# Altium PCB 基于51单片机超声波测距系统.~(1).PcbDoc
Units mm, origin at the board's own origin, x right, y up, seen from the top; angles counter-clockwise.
Board outline 152.4 x 101.6 mm, 2 copper layers (Top Layer, Bottom Layer); 25 components, 33 nets, 135 pads, 0 vias.
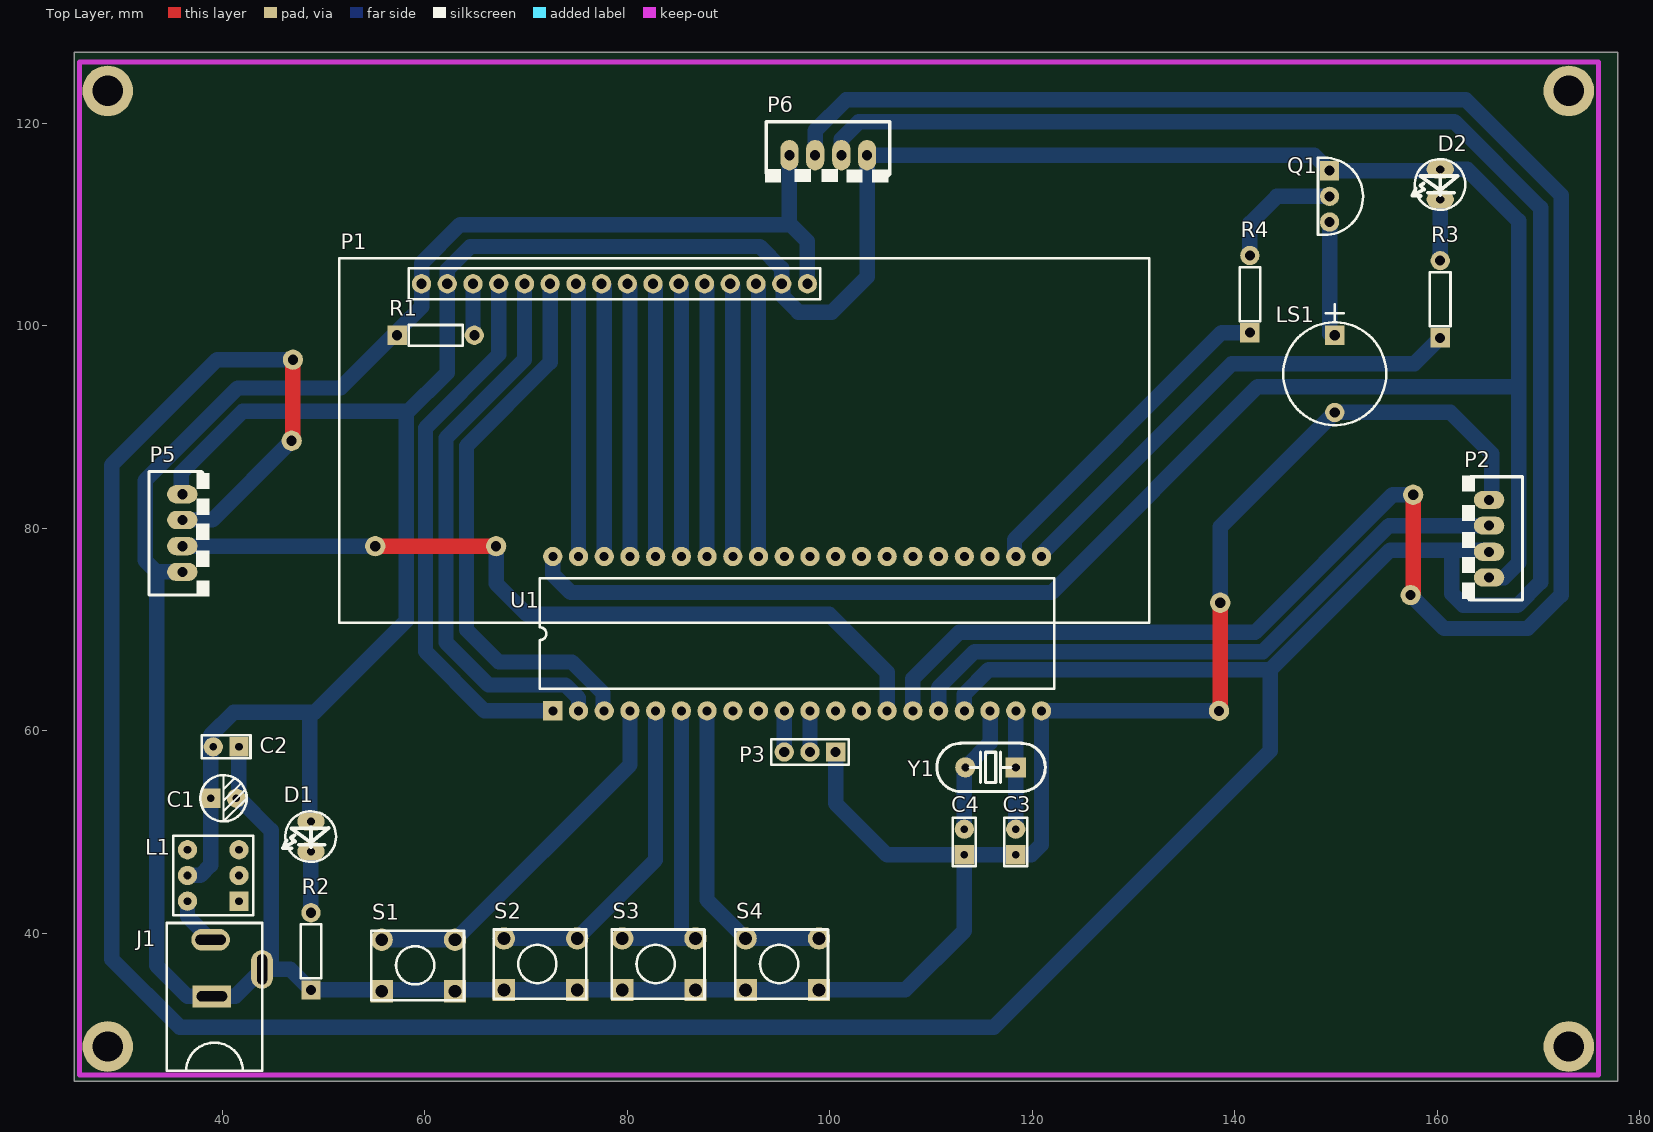
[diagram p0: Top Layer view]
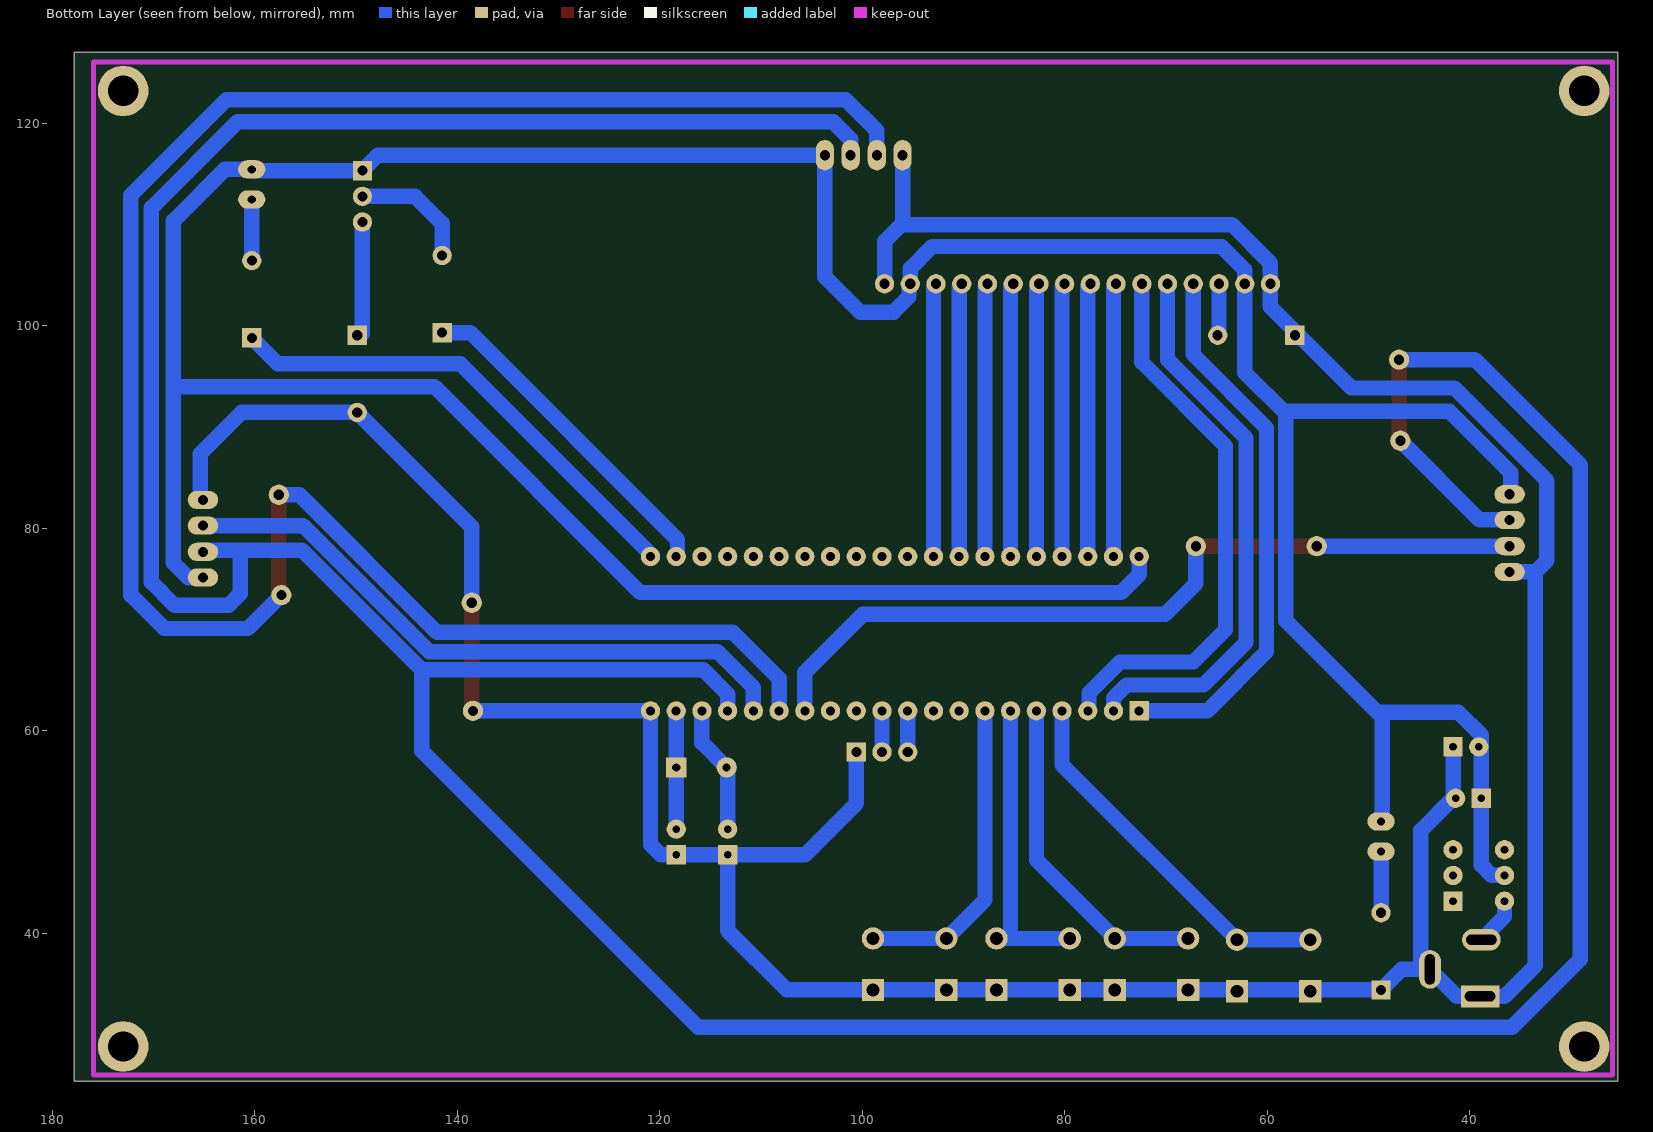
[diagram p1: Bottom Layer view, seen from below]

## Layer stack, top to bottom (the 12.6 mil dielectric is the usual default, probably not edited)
Top Layer: signal copper 0.0356
Dielectric: dielectric 0.32, FR-4, Dk 4.8
Bottom Layer: signal copper 0.0356

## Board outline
25.4,25.4 177.8,25.4 177.8,127 25.4,127

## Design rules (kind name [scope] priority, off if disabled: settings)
Clearance [All] p1: gap=0.254
FabricationTestPointUsage TestPointUsage [All] p1: valid=0 allowmultiple=FALSE
FabricationTestpoint Testpoint [All] p1: side=3 testpointundercomponent=TRUE minsize=1.016 maxsize=2.54 preferedsize=1.524 minholesize=0 maxholesize=1.016 preferedholesize=0.813 testpointgrid=0.025 allowsidetop=TRUE allowsidebottom=TRUE usegrid=TRUE gridtolerance=0
PolygonConnect [All] p1: connectstyle=Relief reliefconductorwidth=0.254 reliefentries=4 polygonreliefangle="90 Angle"
RoutingVias [All] p1: holewidth=0.711 width=1.27 viastyle="Through Hole" minholewidth=0.711 minwidth=1.27 maxholewidth=0.711 maxwidth=1.27
SilkscreenOverComponentPads [All] p1: minsilkscreentomaskgap=0.254
SolderMaskExpansion [All] p1: expansion=0.102
Width [All] p1: maxlimit=2.54 minlimit=0.254 preferedwidth=0.254
25 further rules are at their usual default settings.

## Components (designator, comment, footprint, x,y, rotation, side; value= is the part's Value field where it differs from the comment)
C1 "47uF" 电解电容 40.132,53.34 r0 top
C2 "104" 瓷片电容 39.116,58.42 r180 top
C3 "22pF" 瓷片电容 118.364,50.292 r90 top
C4 "22pF" 瓷片电容 113.284,50.292 r90 top
D1 "LED" 发光二极管 48.768,49.784 r0 top
D2 "LED" 发光二极管 160.274,114.173 r0 top
J1 "PWR2.5" 电源接头 36.322,31.496 r90 top
L1 "电源开关" 开关 39.37,45.72 r180 top
LS1 "Speaker" 蜂鸣器 149.86,99.06 r270 top
P1 "1602" LCD1602液晶 84.328,83.82 r0 top
P2 "Header 4" 4P座 165.1,82.804 r270 top
P3 "程序下载接口" 下载器 100.584,57.912 r180 top
P5 "Header 4" 4P座 36.068,75.692 r90 top
P6 "Header 4" 4P座 96.012,116.84 r0 top
Q1 "8550" 三极管 149.606,115.189 r0 top
R1 "3K" 电阻 60.96,99.06 r90 top
R2 "10K" 电阻 48.768,38.1 r180 top
R3 "1K" 电阻 160.274,102.489 r180 top
R4 "100" 电阻 141.478,102.997 r180 top
S1 "" 按键 59.055,36.957 r90 top
S2 "" 按键 71.12,37.084 r90 top
S3 "" 按键 82.804,37.084 r90 top
S4 "" 按键 94.996,37.084 r90 top
U1 "STC89C51" 51单片机 72.644,61.976 r90 top
Y1 "11.0592MHz" 晶振 118.364,56.388 r180 top

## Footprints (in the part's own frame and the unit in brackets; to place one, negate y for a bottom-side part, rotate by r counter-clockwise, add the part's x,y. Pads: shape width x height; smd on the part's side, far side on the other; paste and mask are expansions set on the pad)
4P座 [mil]
  oval 71x118 hole 39.37: 1(0,0) 2(100,0) 3(202,0) 4(302,0)
  silkscreen extent -96,-106 390,130
51单片机 [mil]
  rect 75x75 hole 35: 1(0,0)
  round 75 hole 35: 2(0,-100) 3(0,-200) 4(0,-300) 5(0,-400) 6(0,-500) 7(0,-600) 8(0,-700) 9(0,-800) 10(0,-900) 11(0,-1000) 12(0,-1100) 13(0,-1200) 14(0,-1300) 15(0,-1400) 16(0,-1500) 17(0,-1600) 18(0,-1700) 19(0,-1800) 20(0,-1900) 21(600,-1900) 22(600,-1800) 23(600,-1700) 24(600,-1600) 25(600,-1500) 26(600,-1400) 27(600,-1300) 28(600,-1200) 29(600,-1100) 30(600,-1000) 31(600,-900) 32(600,-800) 33(600,-700) 34(600,-600) 35(600,-500) 36(600,-400) 37(600,-300) 38(600,-200) 39(600,-100) 40(600,0)
  silkscreen extent 85,-1950 515,50
LCD1602液晶 [mm]
  round 1.905 hole 1: 1(-24.638,20.32) 2(-22.098,20.32) 3(-19.558,20.32) 4(-17.018,20.32) 5(-14.478,20.32) 6(-11.938,20.32) 7(-9.398,20.32) 8(-6.858,20.32) 9(-4.318,20.32) 10(-1.778,20.32) 11(0.762,20.32) 12(3.302,20.32) 13(5.842,20.32) 14(8.382,20.32) 15(10.922,20.32) 16(13.462,20.32)
  silkscreen extent -32.77,-13.16 47.23,22.84
三极管 [mil]
  rect 75x75 hole 39: 1(-10,5)
  round 75 hole 39: 2(-10,-95) 3(-10,-195)
  silkscreen extent -55,-245 120,55
下载器 [mil]
  rect 75x75 hole 39: 1(0,0)
  round 75 hole 39: 2(100,0) 3(200,0)
  silkscreen extent -50,-50 250,50
发光二极管 [mil]
  oval 106x71 hole 31.5: 1(0,50) 2(0,-67)
  silkscreen extent -108,-107 98,89
开关 [mil]
  rect 75x75 hole 30: 1(-90,100)
  round 75 hole 30: 2(110,100) 3(-90,0) 4(110,0) 5(-90,-100) 6(110,-100)
  silkscreen extent -145,-155 165,155
按键 [mm]
  rect 2.2x2.2 hole 1.27: 1(-2.667,3.302) 1(-2.667,-3.937)
  round 2.2 hole 1.27: 2(2.413,3.302) 2(2.413,-3.937)
  silkscreen extent -3.56,-4.83 3.3,4.32
晶振 [mm]
  rect 2x2 hole 0.8: 1(0,0)
  round 2 hole 0.8: 2(4.978,0)
  silkscreen extent -2.92,-2.41 7.8,2.39
瓷片电容 [mil]
  rect 75x75 hole 30: 1(-100,0)
  round 75 hole 30: 2(0,0)
  silkscreen extent -145,-45 45,45
电源接头 [mil]
  oval 85x150 hole 39.37 slot 118.11 at 90 deg: 1(310,-100)
  rect 85x150 hole 39.37 slot 118.11 at 90 deg: 2(90,-105)
  oval 150x85 hole 39.37 slot 118.11 at 0 deg: 2(195,-300)
  silkscreen extent -200,-300 375,70
电解电容 [mil]
  rect 75x75 hole 30: 1(-50,0)
  round 75 hole 30: 2(50,0)
  silkscreen extent -90,-90 90,90
电阻 [mil]
  rect 75x75 hole 39: 1(0,145)
  round 75 hole 39: 2(0,-155)
  silkscreen extent -40,-110 40,100
蜂鸣器 [mil]
  rect 75x75 hole 39: 1(0,0)
  round 75 hole 39: 2(300,0)
  silkscreen extent -120,-200 350,200

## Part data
C1: library part "Cap Pol1", "Polarized Capacitor (Radial)"
C2 C3 C4: library part Cap, "Capacitor"
D1 D2: library part LED0, "Typical INFRARED GaAs LED"
J1: "Low Voltage Power Supply Connector"
L1: library part Liujiao
LS1: "Loudspeaker"
P2 P5 P6: "Header, 4-Pin"
P3: library part "Header 3", "Header, 3-Pin"
Q1: library part 2N3906, "PNP General Purpose Amplifier"
R1 R2 R3 R4: library part Res2, "Resistor"
S1 S2 S3 S4: library part SW-PB, "Switch"
U1: library part STC89C52
Y1: library part XTAL, "Crystal Oscillator"

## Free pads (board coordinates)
  round 5 hole 3: 0(28.702,123.19) 1(172.974,123.19) 2(172.974,28.829) 3(28.702,28.829)
  round 2 hole 1: 0(157.607,83.312) 1(157.353,73.406) 2(67.056,78.232) 3(55.118,78.232) 4(46.99,96.647) 5(46.863,88.646) 6(138.557,72.644) 7(138.43,61.976)

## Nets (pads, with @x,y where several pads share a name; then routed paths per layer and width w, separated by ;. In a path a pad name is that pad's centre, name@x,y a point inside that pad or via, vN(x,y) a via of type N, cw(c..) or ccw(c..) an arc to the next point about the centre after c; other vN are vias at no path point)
ECHO1: P5.2 pad.2@67.056,78.232 pad.3@55.118,78.232 U1.14 | length 80.7
  Top Layer w1.524: pad.3@55.118,78.232 pad.2@67.056,78.232
  Bottom Layer w1.524: P5.2 pad.3@55.118,78.232 ; pad.2@67.056,78.232 67.056,74.549 70.104,71.501 99.949,71.501 105.664,65.786 U1.14
ECHO2: P6.2 pad.0@157.607,83.312 pad.1@157.353,73.406 U1.15 | length 208.4
  Top Layer w1.524: pad.1@157.353,73.406 157.607,73.66 pad.0@157.607,83.312
  Bottom Layer w1.524: P6.2 98.552,119.253 101.6,122.301 162.814,122.301 172.212,112.903 172.212,73.406 168.91,70.104 160.655,70.104 pad.1@157.353,73.406 ; U1.15 108.204,65.151 112.776,69.723 141.986,69.723 155.575,83.312 pad.0@157.607,83.312
ECHO3: P2.2 U1.16 | length 63
  Bottom Layer w1.524: U1.16@110.744,62.23 110.744,64.262 114.3,67.818 142.774,67.818 155.22,80.264 P2.2
GND: C1.2 C2.1 C3.1 C4.1 J1.2 LS1.2 P1.1 P1.16 P2.1 P3.1 P5.1 P6.1 pad.6 pad.7 R1.1 R2.1 S1.1 S2.1 S3.1 S4.1 U1.20 | length 371
  Top Layer w1.524: pad.7 138.557,62.103 pad.6
  Bottom Layer w1.524: P5.1 33.528,75.692 ; C2.1 41.656,53.34 44.831,50.165 44.831,36.449 46.736,36.449 R2.1 67.818,34.417 75.057,34.417 79.502,34.417 86.741,34.417 91.694,34.417 98.933,34.417 107.442,34.417 113.284,40.259 C4.1 ; J1.2@43.942,36.449 41.275,33.782 38.989,33.782 36.576,33.782 33.528,36.83 33.528,75.692 ; P6.1 96.012,110.109 96.139,109.982 ; P1.16 97.79,108.331 96.139,109.982 ; P3.1 100.584,52.832 105.664,47.752 C4.1 ; pad.7 U1.20 120.904,48.768 119.888,47.752 C3.1 C4.1 ; pad.6 138.557,80.137 LS1.2 161.29,91.44 165.354,87.376 P2.1@165.354,82.804 ; 33.528,75.692 32.385,76.835 32.385,84.709 41.529,93.853 51.689,93.853 59.69,101.854 P1.1 59.69,106.172 63.5,109.982 96.139,109.982
NetD1_2: D1.2 R2.2 | length 6
  Bottom Layer w1.524: R2.2 D1.2
NetD2_2: D2.2 R3.2 | length 6
  Bottom Layer w1.524: R3.2 D2.2
NetJ1_1: J1.1 L1.2 | length 4.8
  Bottom Layer w1.5: L1.2 36.576,41.656 J1.1
NetLS1_1: LS1.1 Q1.3 | length 11
  Bottom Layer w1.524: LS1.1@149.352,99.187 Q1.3
NetP1_3: P1.3 R1.2 | length 5.1
  Bottom Layer w1.5: P1.3 64.77,99.187 R1.2
NetQ1_2: Q1.2 R4.2 | length 12.2
  Bottom Layer w1.524: R4.2 141.478,110.109 144.145,112.776 Q1.2
P00: P1.7 U1.39 | length 27
  Bottom Layer w1.5: P1.7 75.184,103.886 U1.39
P01: P1.8 U1.38 | length 27
  Bottom Layer w1.5: P1.8 77.724,103.886 U1.38
P02: P1.9 U1.37 | length 27
  Bottom Layer w1.5: P1.9 80.264,103.886 U1.37
P03: P1.10 U1.36 | length 27
  Bottom Layer w1.5: P1.10 82.804,103.886 U1.36
P04: P1.11 U1.35 | length 27
  Bottom Layer w1.5: P1.11 85.344,103.886 U1.35
P05: P1.12 U1.34 | length 27
  Bottom Layer w1.5: P1.12 87.884,103.886 U1.34
P06: P1.13 U1.33 | length 27
  Bottom Layer w1.5: P1.13 90.424,103.886 U1.33
P07: P1.14 U1.32 | length 27
  Bottom Layer w1.5: P1.14 92.964,103.886 U1.32
P10: P1.4 U1.1 | length 54.3
  Bottom Layer w1.5: P1.4 67.31,97.155 60.071,89.916 60.071,67.818 65.913,61.976 U1.1
P11: P1.5 U1.2 | length 55.3
  Bottom Layer w1.5: P1.5 69.85,96.647 62.103,88.9 62.103,68.707 66.294,64.516 73.914,64.516 75.184,63.246 U1.2
P12: P1.6 U1.3 | length 55
  Bottom Layer w1.5: P1.6 72.39,96.393 64.135,88.138 64.135,69.977 67.31,66.802 74.549,66.802 77.597,63.754 U1.3@77.597,62.357
P13: S1.2 U1.4 | length 37
  Bottom Layer w1.5: S1.2@55.753,39.37 62.992,39.37 80.264,56.642 U1.4
P14: S2.2 U1.5 | length 32.9
  Bottom Layer w1.5: S2.2@67.818,39.497 75.057,39.497 82.804,47.244 U1.5
P15: S3.2 U1.6 | length 29.6
  Bottom Layer w1.5: S3.2@79.502,39.497 S3.2@86.741,39.497 ; 85.344,39.624 U1.6
P16: S4.2 U1.7 | length 31.3
  Bottom Layer w1.5: U1.7 87.884,43.307 91.694,39.497 S4.2@98.933,39.497
P20: R3.1 U1.21 | length 48.5
  Bottom Layer w1.524: U1.21 120.904,77.47 139.7,96.266 157.734,96.266 R3.1
P21: R4.1 U1.22 | length 33.4
  Bottom Layer w1.524: U1.22 118.237,77.343 118.237,78.867 138.684,99.314 R4.1
RX: P3.3 U1.10 | length 4.1
  Bottom Layer w1.524: P3.3 U1.10
TRIG: P2.3 P5.3 P6.3 pad.4 pad.5 U1.17 | length 417.3
  Top Layer w1.524: pad.5 46.99,88.773 pad.4
  Bottom Layer w1.524: 29.083,71.755 29.083,69.977 ; P5.3 39.04,80.823 pad.5 ; pad.4 39.497,96.647 29.083,86.233 29.083,69.977 ; P6.3 101.143,118.415 102.87,120.142 161.671,120.142 170.18,111.633 170.18,74.676 167.894,72.39 162.56,72.39 161.417,73.533 161.417,77.851 ; U1.17 113.284,63.627 115.697,66.04 143.51,66.04 ; P2.3@165.354,77.851 161.417,77.851 ; 29.083,69.977 29.083,37.465 35.814,30.734 116.205,30.734 143.51,58.039 143.51,66.04 ; 143.51,66.04 155.321,77.851 161.417,77.851
TX: P3.2 U1.11 | length 4.1
  Bottom Layer w1.524: P3.2 U1.11
VCC: C1.1 C2.2 D1.1 D2.1 L1.4 P1.2 P1.15 P2.4 P5.4 P6.4 Q1.1 U1.40 | length 383.6
  Bottom Layer w1.524: P5.4@35.941,83.363 35.941,85.471 42.037,91.567 57.912,91.567 58.166,91.313 ; L1.4 37.846,45.72 38.862,46.736 C1.1 38.862,59.563 41.148,61.849 48.641,61.849 ; D1.1@48.641,51.435 48.641,61.849 ; U1.40 72.644,75.438 74.422,73.66 121.92,73.66 142.24,93.98 167.767,93.98 ; P2.4@165.354,75.133 166.573,75.133 168.021,76.581 168.021,110.363 162.941,115.443 D2.1 160.147,115.316 Q1.1 147.828,116.84 P6.4 103.683,104.826 100.203,101.346 96.901,101.346 95.377,102.87 95.377,104.013 P1.15 95.25,105.664 93.091,107.823 64.516,107.823 62.23,105.537 P1.2 62.23,95.377 58.166,91.313 ; 48.641,61.849 49.149,61.849 58.166,70.866 58.166,91.313
X1: C3.2 U1.19 Y1.1 | length 11.7
  Bottom Layer w1.524: C3.2 Y1.1 U1.19
X2: C4.2 U1.18 Y1.2 | length 12.7
  Bottom Layer w1.524: C4.2 113.284,56.286 Y1.2 115.824,58.826 U1.18
pads on no net: L1.1 L1.3 L1.5 L1.6 U1.8 U1.9 U1.12 U1.13 U1.23 U1.24 U1.25 U1.26 U1.27 U1.28 U1.29 U1.30 U1.31

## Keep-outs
Keep-Out Layer:
  lines w0.5: 175.895,126.035 175.895,26.035 25.908,26.035 25.908,126.035 175.908,126.035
